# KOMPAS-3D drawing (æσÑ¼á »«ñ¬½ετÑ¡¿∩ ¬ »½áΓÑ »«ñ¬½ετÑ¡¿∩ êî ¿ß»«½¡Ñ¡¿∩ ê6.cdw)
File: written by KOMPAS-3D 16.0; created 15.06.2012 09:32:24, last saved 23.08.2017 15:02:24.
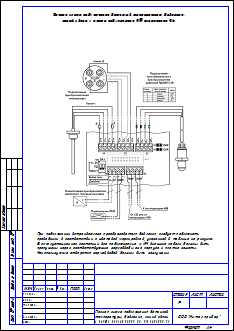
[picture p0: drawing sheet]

Sheet 1: A4, portrait

Title block, sheet 1: sheets: 29; organisation: ООО"Интелприбор"; sheet format: A4; stored path: D:\Общее для проектов\Шаблон проекта\5-ти трубная система\5-х трубная шаблон.cdw; cell 51: МО, Воскресенсикй р-н, п. Хорлово, ул. Интернациональная, д. 4; cell 320: Р

Views: Вид 2, Вид 3
Referenced files in C:\Users\chesnokov\Desktop\плаза\: Подключения к ИМ.png
Referenced files in C:\Program Files (x86)\ASCON\KOMPAS-3D V16\Sys\: spds.lcs, EngSys.lcs, GRAPHIC.LHS
Referenced files: graphic.tdp
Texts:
  Смирнов В.С.
  УУ-3423
  GOST Common
  Normal
  List Paragraph
  heading 3
  для схемы
  txt
  Т0-элементы
  Полная схема подключения датчиков температуры, давления,
  линий связи к плате подключения ИМ исполнения И6:
  При подключении встраиваемого преобразователя давления следует подключать
  проводники в соответствии с цветовой маркировкой, указанной в таблице на рисунке.
  В эксплуатационнос состоянии все подключаемые к ИМ внешние кабели должны быть
  пропущены через соответствующие гермовводы его корпуса и плотно зажаты.
  Неиспользуемые отверстия гермовводов должны быть заглушены.
  Размеры, параметризация
  сит. план
  подача ГВС
  обратка ГВС
  хвс
  обратка
  POLYLINE_STYLE_0.25_RGB_0_0_0
  стены
  Основная (не является границей для штриховки)
  POLYLINE_STYLE_0.18_RGB_0_0_0
  ХВС
  зеленая
  Красная тонкая
  арматура
  Подача
  Скрытая линия
  Ось Z
  Ось Y
  Ось X
  Образующая трубопровода (проектируемого)
  Трубопровод толщиной 0.6мм (одна линия)
  Трубопровод толщиной 1.2мм (одна линия)
  Трубопровод толщиной 1.0мм (одна линия)
  Трубопровод толщиной 0.8мм (одна линия)
  Трубопровод существующий (одна линия)
  Трубопровод невидимый (одна линия)
  Трубопровод демонтируемый (одна линия)
  Осевая трубопровода
  Осевая трубопровода (демонтируемого)
  Образующая трубопровода (существующего)
  Образующая трубопровода (невидимого)
  Изолированный трубопровод проектируемый (одна линия)
  Изолированный трубопровод существующий (одна линия)
  Образующая изоляции
  Изоляция
  Изолированный трубопровод невидимый (одна линия)
  Штрих пвс 075
  штрих пвс 2,5
  существующее оборудование
  Существующее оборудование
  K5LT_BASIC_RGB_0_0_255_THICK_0.53
  POLYLINE_STYLE_1.51_RGB_0_0_255
  POLYLINE_STYLE_0.50_RGB_128_128_128
  K5LT_AXLED_RGB_255_128_0_SC_1_THICK_0.18
  ACAD_ISO04W100_RGB_0_0_0_SC_1_THICK_0.18
  тонкая черная
  тонкая красная
  тонкая синяя
  тонкая оранж
  красн штрих
  пломбировка
  Провода
  синий штрих
  Стили документа
  G2co
  расход вторичной воды объемный
  расход вторичной воды объемный при 70гр
  Gco
  расход теплоносителя массовый
  расход теплоносит объемн подающ
  расход теплоносит объемн обр
  Лапир
  Ghvs
  Im1
  Im2
  Im3
  Im4
  Im5
  Khvs
  норматив ХВС
  число подъездов
  число этажей
  Nkv
  число квартир
  тепловая нагрузка на отопление
  сумма Q
  Qgvs
  тепловая нагрузка ГВС
  тепловая нагрузка на циркуляцию ГВС
  иммитовставка или под манометр
  ro1
  ro2
  ro3
  ro4
  верх предел темп граф
  нижн предел темп граф
  темп подачи ГВС
  темп обр ГВС
  темр хол воды
  vzdh
  Kchn
  Ktp
  Knp
  tnv
  Vклап
  KLP
  RPD
  RDS
  PUMP
  ro5
  beta
  tnv98
  Shifr
  Переход ГОСТ 17378-2001
  Переход
  ГОСТ
  Сталь 09Г2С ГОСТ 19281-89
  Втулка 20x50
  Лит-Масса-Масштаб
  Материал-Предприятие
  Title Specification
  Body Specification ( left align )
  Body Specificaton ( centered )
  Поз.
  Кол.
  Приме-
  чание
  Таблица спецификации
  Засыпка
  Штрих3
  Штрих2
  Штрих1
  Песок
  Штр0.5пр7
  Штр0.5пр12
  Штр0.3пр10
  Штр1.4пр21.21
  Штр1пр15
  Штр2.12пр35
  Штр1.5пр25
  Штр2.82пр42.42
  Штр2пр30
  SACNCR_ISO 1
  Электрощитовая
  Пр-1
  Ок-1
  Обозначение стандарта
  Типоразмер
  Пояснительная записка
  Разраб.
  Пров.
  Т.контр.
  Н.контр.
  Утв.
  Полная схема подключения датчиков
  температуры, давления, линий связи
  к плате подключения ИМ исполнения И6
  Рабочие чертежи основного комплекта. ГОСТ Р 21.1101-2009 Ф3
  Стадия
  Лист
  Листов
  Изм.
  Кол.уч.
  №док.
  Подп.
  Дата
  Изменение
  Номер документа
  Подпись
  Наименование объекта строительства, в состав которого входит здание, наим. микр
  Наименование здания (сооружения)
  Порядковый номер листа
  Количество листов в документе
  Наименование изображения
  Индекс предприятия, выпускающего документ
  Инв. № подл.
  Подп. и дата
  Взам. инв. №
  Инвентарный номер подлинника
  Подпись принявшего подлинник на хранение
  Инвентарный номер подлинника, взамен которого выпущен данный подлинник
  Согласовано
  Формат листа
  Согласование
  03 Рабочие чертежи основного комплекта. ГОСТ Р 21.1101-2009 Ф3
Dimensions and other numbers on the sheet: 09Г2С; 1; 20; 5; 29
